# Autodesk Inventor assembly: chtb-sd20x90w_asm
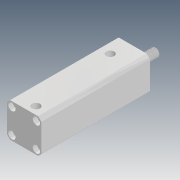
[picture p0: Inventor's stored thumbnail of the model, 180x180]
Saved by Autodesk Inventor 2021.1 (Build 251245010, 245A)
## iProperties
Company: Microsoft
Created: 2018-05
Part Number: chtb-sd20x90w_asm
Description: STEP AP214
Document SubType Name: Assembly
Designer: user
Title: chtb-sd20x90w_asm.STEP
Author: Windows
Revision Number: ÈÎºÎ
Sending System: SolidWorks 2015
Preprocessor: SwSTEP 2.0
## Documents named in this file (4)
- D:\Vault_2016\Projekty\Clamptek\Hydraulic\CHTB\CHTB-20\Inventor\CHTB-SD20x90W\chtb-sd20x90w_asm.iam
- D:\Vault_2016\Projekty\Clamptek\Hydraulic\CHTB\CHTB-20\Inventor\CHTB-SD20x90W\CHTB-SD20X90NBT.ipt
- D:\Vault_2016\Projekty\Clamptek\Hydraulic\CHTB\CHTB-20\Inventor\CHTB-SD20x90W\CHTB-SD20X90WHSG.ipt
- D:\Vault_2016\Projekty\Clamptek\Hydraulic\CHTB\CHTB-20\Inventor\CHTB-SD20x90W\QG.ipt
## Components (3 placed, 3 different names)
1. CHTB-SD20X90NBT_1
2. CHTB-SD20X90WHSG_2
3. QG_3
